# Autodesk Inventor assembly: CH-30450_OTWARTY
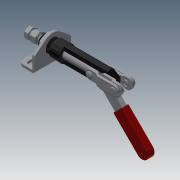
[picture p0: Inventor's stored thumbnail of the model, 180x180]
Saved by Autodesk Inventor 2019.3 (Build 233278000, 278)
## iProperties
Company: ·L?¤¤?
Created: 2010-06
Part Number: CH-30450_OTWARTY
Material: Ogólny
Description: STEP AP203
Document SubType Name: Assembly
Designer: CADENGINEERING4
Sending System: SolidWorks 2005179
Preprocessor: SwSTEP 2.0
Title: CH-30450.STEP
Author: ·L?¥Î?
Revision Number: ANY
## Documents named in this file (13)
- D:\Vault_2016\Projekty\STRONA\Push-pull clamp\CH-30450\CH-30450_OTWARTY.iam
- D:\Vault_2016\Projekty\STRONA\Push-pull clamp\CH-30450\CH-30450-04___.ipt
- D:\Vault_2016\Projekty\STRONA\Push-pull clamp\CH-30450\CH-30450-10___.ipt
- D:\Vault_2016\Projekty\STRONA\Push-pull clamp\CH-30450\CH-30450-08___.ipt
- D:\Vault_2016\Projekty\STRONA\Push-pull clamp\CH-30450\CH-30450-07___.ipt
- D:\Vault_2016\Projekty\STRONA\Push-pull clamp\CH-30450\CH-30450-05___.ipt
- D:\Vault_2016\Projekty\STRONA\Push-pull clamp\CH-30450\CH-30450-09___.ipt
- D:\Vault_2016\Projekty\STRONA\Push-pull clamp\CH-30450\CH-30450-06___.ipt
- D:\Vault_2016\Projekty\STRONA\Push-pull clamp\CH-30450\M12X30___.ipt
- D:\Vault_2016\Projekty\STRONA\Push-pull clamp\CH-30450\CH-30450-02___.ipt
- D:\Vault_2016\Projekty\STRONA\Push-pull clamp\CH-30450\M12___.ipt
- D:\Vault_2016\Projekty\STRONA\Push-pull clamp\CH-30450\CH-30450-01___.ipt
- D:\Vault_2016\Projekty\STRONA\Push-pull clamp\CH-30450\CH-30450-03___.ipt
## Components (14 placed, 14 different names)
1. CH-30450-04_??_1 — Zestawiające:13, Zestawiające:14, Zestawiające:15, Zestawiające:17, Zestawiające:20, Zestawiające:21, Zestawiające:24, Zestawiające:25
2. CH-30450-10_??_2 — Zestawiające:8, Zestawiające:9, Zestawiające:10
3. CH-30450-08_??_3 — Zestawiające:18, Zestawiające:19
4. CH-30450-07_??_4 — Zestawiające:22, Zestawiające:23
5. CH-30450-05_??_5 — Zestawiające:5, Zestawiające:7, Kątowe:1, Zestawiające:11, Zestawiające:12, Zestawiające:27, Zestawiające:28, Kątowe:2
6. CH-30450-09_??_6 — Zestawiające:24, Zestawiające:25
7. CH-30450-06_??_7 — Zestawiające:5, Zestawiające:6
8. M12X30_??_8 — Zestawiające:1, Zestawiające:2, Zestawiające:3
9. CH-30450-02_??_9 — Zestawiające:3, Zestawiające:4, Zestawiające:17, Zestawiające:27
10. M12_??_10 — Zestawiające:1, Zestawiające:2, Zestawiające:4
11. CH-30450-07_??_11 — Zestawiające:20, Zestawiające:21, Zestawiające:26
12. CH-30450-01_??_12 — Zestawiające:6, Zestawiające:7, Kątowe:1, Zestawiające:28
13. CH-30450-03_??_13 — Zestawiające:8, Zestawiające:9, Zestawiające:10, Zestawiające:11, Zestawiające:12, Zestawiające:15, Zestawiające:16, Zestawiające:18, Zestawiające:19, Zestawiające:26, Kątowe:2
14. CH-30450-04_??_14 — Zestawiające:13, Zestawiające:14, Zestawiające:16, Zestawiające:22, Zestawiające:23
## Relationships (30: Mate 28, Angle 2)
- Zestawiające:1 [Mate]: M12X30_??_8 ↔ M12_??_10
- Zestawiające:2 [Mate]: M12X30_??_8 ↔ M12_??_10
- Zestawiające:3 [Mate]: M12X30_??_8 ↔ CH-30450-02_??_9
- Zestawiające:4 [Mate]: CH-30450-02_??_9 ↔ M12_??_10
- Zestawiające:5 [Mate]: CH-30450-05_??_5 ↔ CH-30450-06_??_7
- Zestawiające:6 [Mate]: CH-30450-06_??_7 ↔ CH-30450-01_??_12
- Zestawiające:7 [Mate]: CH-30450-05_??_5 ↔ CH-30450-01_??_12
- Zestawiające:8 [Mate]: CH-30450-10_??_2 ↔ CH-30450-03_??_13
- Zestawiające:9 [Mate]: CH-30450-10_??_2 ↔ CH-30450-03_??_13
- Zestawiające:10 [Mate]: CH-30450-10_??_2 ↔ CH-30450-03_??_13
- Kątowe:1 [Angle]: CH-30450-05_??_5 ↔ CH-30450-01_??_12
- Zestawiające:11 [Mate]: CH-30450-05_??_5 ↔ CH-30450-03_??_13
- Zestawiające:12 [Mate]: CH-30450-05_??_5 ↔ CH-30450-03_??_13
- Zestawiające:13 [Mate]: CH-30450-04_??_1 ↔ CH-30450-04_??_14
- Zestawiające:14 [Mate]: CH-30450-04_??_1 ↔ CH-30450-04_??_14
- Zestawiające:15 [Mate]: CH-30450-04_??_1 ↔ CH-30450-03_??_13
- Zestawiające:16 [Mate]: CH-30450-03_??_13 ↔ CH-30450-04_??_14
- Zestawiające:17 [Mate]: CH-30450-04_??_1 ↔ CH-30450-02_??_9
- Zestawiające:18 [Mate]: CH-30450-08_??_3 ↔ CH-30450-03_??_13
- Zestawiające:19 [Mate]: CH-30450-08_??_3 ↔ CH-30450-03_??_13
- Zestawiające:20 [Mate]: CH-30450-04_??_1 ↔ CH-30450-07_??_11
- Zestawiające:21 [Mate]: CH-30450-04_??_1 ↔ CH-30450-07_??_11
- Zestawiające:22 [Mate]: CH-30450-07_??_4 ↔ CH-30450-04_??_14
- Zestawiające:23 [Mate]: CH-30450-07_??_4 ↔ CH-30450-04_??_14
- Zestawiające:24 [Mate]: CH-30450-04_??_1 ↔ CH-30450-09_??_6
- Zestawiające:25 [Mate]: CH-30450-04_??_1 ↔ CH-30450-09_??_6
- Zestawiające:26 [Mate]: CH-30450-07_??_11 ↔ CH-30450-03_??_13
- Zestawiające:27 [Mate]: CH-30450-05_??_5 ↔ CH-30450-02_??_9
- Zestawiające:28 [Mate]: CH-30450-05_??_5 ↔ CH-30450-01_??_12
- Kątowe:2 [Angle]: CH-30450-05_??_5 ↔ CH-30450-03_??_13
